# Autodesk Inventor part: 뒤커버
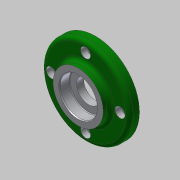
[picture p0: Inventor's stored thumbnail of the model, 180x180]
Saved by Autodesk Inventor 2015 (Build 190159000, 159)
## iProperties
Created: 2019-01
Part Number: 뒤커버
Material: 알루미늄 6061
Document SubType Name: Modeling
Designer: mduedu
Density: 1 g/cm^3
Appearance: 알루미늄 - 평지
Author: mduedu
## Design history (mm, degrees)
sketch "스케치1"
  geometry: L1 (0, 0)-(6, 0); L2 (6, 0)-(6, 20); L3 (6, 20)-(0, 20); L4 (0, 20)-(0, 0); L5 (6, 0)-(14, 0); L6 (14, 0)-(14, 35); L7 (14, 35)-(6, 35); L8 (6, 35)-(6, 0); L9 (14, 0)-(19, 0); L10 (19, 0)-(19, 20); L11 (19, 20)-(14, 20); L12 (14, 20)-(14, 0)
  constraints: 24 end point, 6 parallel, 3 horizontal, 3 perpendicular
  dimensions: "d6" = 70 diameter of L7 L5; "d8" = 40 diameter of L3 L1; "d9" = 40 diameter of L11 L9; "d10" = 5 distance of L10.end L11.end; "d11" = 6 distance of L2.end L3.end; "d12" = 19 distance between parallel lines of L4 L10; "d13" = 8 distance of L6.end L7.end (derived)
revolve "회전1" sketch "스케치1" stored, may be unused: angle "d5" = 90 deg
sketch "스케치2" dims "d14" = 55
  geometry: 7 further points
  constraints: 2 coincident, 2 vertical alignment, 7 other
  dimensions: "d17" = 360 deg dimension on point (0, 0) point (0, 27.5) (derived)
sketch "스케치3"
  geometry: 4 further points
  constraints: 4 other
hole "구멍1" sketch "스케치3" at (0, 27.5), (-27.5, 0), (27.5, 0), (0, -27.5) diameter "d19" = 4.5; stored, may be unused: countersink angle "d23" = 90 deg, drill point angle "d25" = 0 deg; dims "d20" = 6, "d21" = 8, "d22" = 4.6, "d24" = 8
fillet "모깎기1" dims "d26" = 3
sketch "스케치4"
  geometry: C1 r 9.5 at (0, 0); 1 further point
  constraints: 1 centre point, 1 coincident
  dimensions: "d27" = 19 diameter of C1
extrude "돌출1" cut sketch "스케치4" stored distance "d28" = 10; taper "d29" = 0 deg
sketch "스케치5"
  geometry: C1 r 15 at (0, 0); 1 further point
  constraints: 1 centre point, 1 coincident
  dimensions: "d31" = 30 diameter of C1
extrude "돌출2" cut sketch "스케치5" distance "d32" = 8.3; taper "d33" = 0 deg
chamfer "모따기1" distance "d34" = 0.8; stored, may be unused: second distance "d35" = 2, angle "d36" = 30 deg
fillet "모깎기2" dims "d37" = 3
fillet "모깎기3" dims "d38" = 0.5
sketch "스케치6"
  geometry: C1 r 16.5 at (0, 0); 1 further point
  constraints: 1 centre point, 1 coincident
  dimensions: "d39" = 33 diameter of C1
extrude "돌출3" cut sketch "스케치6" distance "d40" = 5; taper "d41" = 0 deg
fillet "모깎기4" dims "d42" = 3
chamfer "모따기2" distance "d43" = 1; stored, may be unused: second distance "d44" = 2, angle "d45" = 30 deg
node "솔리드1"
